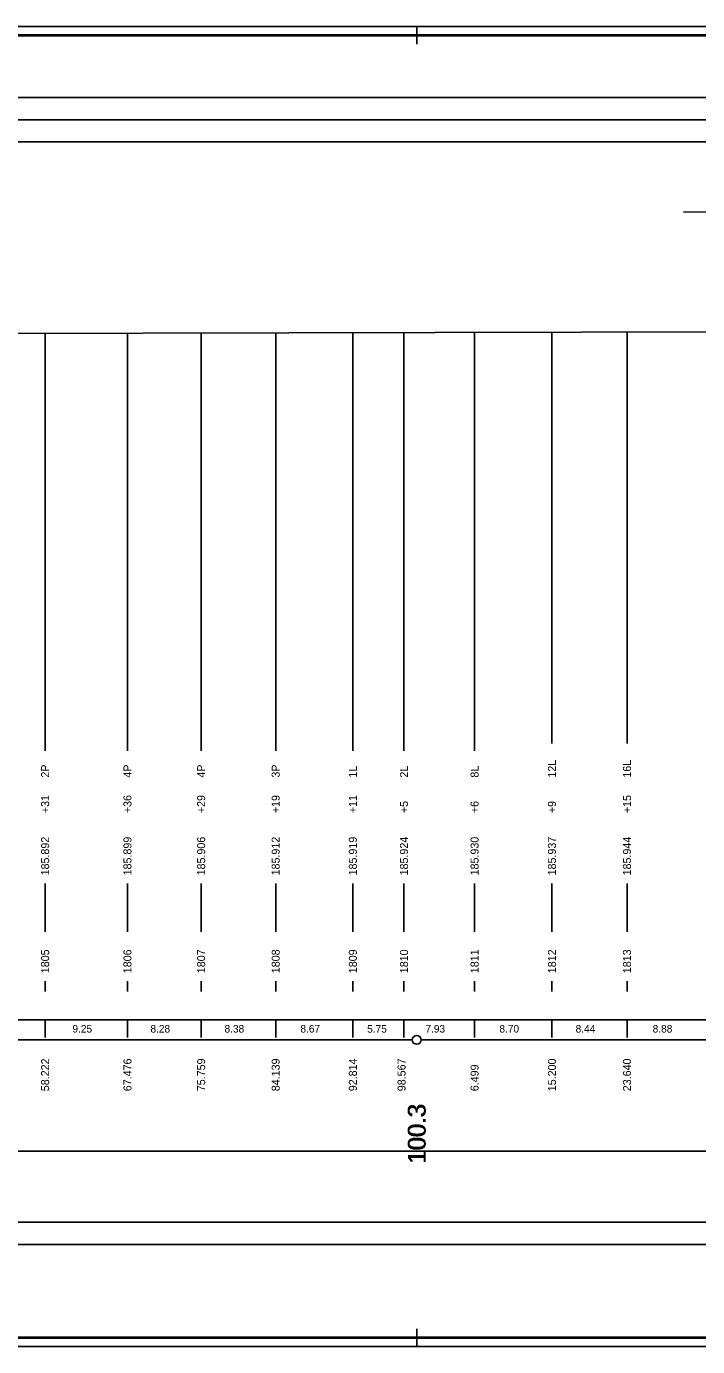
# Model space of a CAD drawing. Extents: x 0 to 10087, y -805 to 297.
# Drawn here: x 7892.2 to 8043.1, y 0 to 297 of the extents above; entities that cross this region are included whole.
import ezdxf

# ---------------------------------------------------------------- set-up
doc = ezdxf.new("R2010")
doc.units = 0
for name, color, linetype in [('CARKY_HODNOT', 7, 'Continuous'), ('KRIV1_CARA', 7, 'Continuous'), ('NIVELETA_CARA', 7, 'Continuous'), ('RAM', 7, 'Continuous'), ('REZERVA', 7, 'Continuous'), ('STAN_CARA', 7, 'Continuous'), ('STAN_PAS', 7, 'Continuous'), ('STAN_TEXT', 7, 'Continuous'), ('TEXT', 7, 'Continuous'), ('TXT_C_BODU', 7, 'Continuous')]:
    doc.layers.add(name, color=color, linetype=linetype)

msp = doc.modelspace()

# ---------------------------------------------------------------- linework, layer by layer
at = {"layer": 'CARKY_HODNOT'}
for p, q in [((7896.44, 138.35), (7896.44, 227.96)), ((7914.95, 138.35), (7914.95, 227.99)), ((7931.52, 138.35), (7931.52, 228.03)), ((7948.28, 138.35), (7948.28, 228.06)), ((7965.63, 138.35), (7965.63, 228.1)), ((7977.13, 138.35), (7977.13, 228.12)), ((7993, 138.35), (7993, 228.15)), ((8010.4, 138.35), (8010.4, 228.19)), ((8027.28, 138.35), (8027.28, 228.22)), ((7896.44, 134), (7896.44, 138.35)), ((7914.95, 134), (7914.95, 138.35)), ((7931.52, 134), (7931.52, 138.35)), ((7948.28, 134), (7948.28, 138.35)), ((7965.63, 134), (7965.63, 138.35)), ((7977.13, 134), (7977.13, 138.35)), ((7993, 134), (7993, 138.35)), ((8010.4, 135.65), (8010.4, 138.35)), ((8027.28, 135.65), (8027.28, 138.35)), ((7896.44, 93.3), (7896.44, 104.2)), ((7914.95, 93.3), (7914.95, 104.2)), ((7931.52, 93.3), (7931.52, 104.2)), ((7948.28, 93.3), (7948.28, 104.2)), ((7965.63, 93.3), (7965.63, 104.2)), ((7977.13, 93.3), (7977.13, 104.2)), ((7993, 93.3), (7993, 104.2)), ((8010.4, 93.3), (8010.4, 104.2)), ((8027.28, 93.3), (8027.28, 104.2)), ((7896.44, 79.9), (7896.44, 82.2)), ((7914.95, 79.9), (7914.95, 82.2)), ((7931.52, 79.9), (7931.52, 82.2)), ((7948.28, 79.9), (7948.28, 82.2)), ((7965.63, 79.9), (7965.63, 82.2)), ((7977.13, 79.9), (7977.13, 82.2)), ((7993, 79.9), (7993, 82.2)), ((8010.4, 79.9), (8010.4, 82.2)), ((8027.28, 79.9), (8027.28, 82.2))]:
    msp.add_line(p, q, dxfattribs=at)
at = {"layer": 'KRIV1_CARA'}
msp.add_line((7811.8, 44), (8321.33, 44), dxfattribs=at)
at = {"layer": 'NIVELETA_CARA'}
for p, q in [((300, 281), (8321.33, 281)), ((300, 276), (8321.33, 276)), ((300, 271), (8321.33, 271)), ((8067.97, 255.3), (8039.97, 255.24)), ((7721.21, 227.61), (8065.75, 228.3)), ((500, 28), (8321.33, 28)), ((500, 23), (8321.33, 23))]:
    msp.add_line(p, q, dxfattribs=at)
at = {"layer": 'RAM'}
for p, q in [((8636.33, 297), (0, 297)), ((7980, 293), (7980, 297)), ((8634.33, 295.1), (2, 295.1)), ((8634.33, 295), (2, 295)), ((8634.33, 294.9), (2, 294.9)), ((7980, 0), (7980, 4)), ((0, 0), (8636.33, 0)), ((2, 2.1), (8634.33, 2.1)), ((2, 2), (8634.33, 2)), ((2, 1.9), (8634.33, 1.9))]:
    msp.add_line(p, q, dxfattribs=at)
at = {"layer": 'REZERVA'}
msp.add_circle((7980, 69), 1, dxfattribs=at)
at = {"layer": 'STAN_CARA'}
for p, q in [((7781, 69), (7979, 69)), ((7981, 69), (8179, 69))]:
    msp.add_line(p, q, dxfattribs=at)
at = {"layer": 'STAN_PAS'}
for p, q in [((300, 73.5), (8321.33, 73.5)), ((7896.44, 69.5), (7896.44, 73.5)), ((7914.95, 69.5), (7914.95, 73.5)), ((7931.52, 69.5), (7931.52, 73.5)), ((7948.28, 69.5), (7948.28, 73.5)), ((7965.63, 69.5), (7965.63, 73.5)), ((7977.13, 69.5), (7977.13, 73.5)), ((7993, 69.5), (7993, 73.5)), ((8010.4, 69.5), (8010.4, 73.5)), ((8027.28, 69.5), (8027.28, 73.5))]:
    msp.add_line(p, q, dxfattribs=at)

# ---------------------------------------------------------------- texts
at = {"layer": 'STAN_TEXT'}
for s, p in [('9.25', (7902.58, 70.65)), ('8.28', (7920.12, 70.65)), ('8.38', (7936.78, 70.65)), ('8.67', (7953.84, 70.65)), ('5.75', (7968.84, 70.63)), ('7.93', (7981.95, 70.65)), ('8.70', (7998.58, 70.65)), ('8.44', (8015.72, 70.65)), ('8.88', (8033.04, 70.65))]:
    msp.add_text(s, height=1.7, dxfattribs=at).set_placement(p)
for s, height, p in [('58.222', 1.8, (7897.34, 57.45)), ('67.476', 1.8, (7915.85, 57.45)), ('75.759', 1.8, (7932.42, 57.45)), ('84.139', 1.8, (7949.18, 57.45)), ('92.814', 1.8, (7966.53, 57.45)), ('98.567', 1.8, (7977.48, 57.45)), ('6.499', 1.8, (7993.9, 57.45)), ('15.200', 1.8, (8011.3, 57.45)), ('23.640', 1.8, (8028.18, 57.45)), ('   100.3', 4, (7982, 36.84)), ('   100.3', 4, (7982, 36.74)), ('   100.3', 4, (7982, 36.64))]:
    msp.add_text(s, height=height, rotation=90, dxfattribs=at).set_placement(p)
at = {"layer": 'TEXT'}
for s, p in [('2P', (7897.34, 128)), ('4P', (7915.85, 128)), ('4P', (7932.42, 128)), ('3P', (7949.18, 128)), ('12L', (8011.3, 128)), ('16L', (8028.18, 128)), ('1L', (7966.53, 128)), ('2L', (7978.03, 128)), ('8L', (7993.9, 128)), ('+31', (7897.34, 120)), ('+36', (7915.85, 120)), ('+29', (7932.42, 120)), ('+19', (7949.18, 120)), ('+11', (7966.53, 120)), ('+5', (7978.03, 120)), ('+6', (7993.9, 120)), ('+9', (8011.3, 120)), ('+15', (8028.18, 120)), ('185.892', (7897.34, 106)), ('185.899', (7915.85, 106)), ('185.906', (7932.42, 106)), ('185.912', (7949.18, 106)), ('185.919', (7966.53, 106)), ('185.924', (7978.03, 106)), ('185.930', (7993.9, 106)), ('185.937', (8011.3, 106)), ('185.944', (8028.18, 106))]:
    msp.add_text(s, height=1.8, rotation=90, dxfattribs=at).set_placement(p)
at = {"layer": 'TXT_C_BODU'}
for s, p in [('1805', (7897.34, 84)), ('1806', (7915.85, 84)), ('1807', (7932.42, 84)), ('1808', (7949.18, 84)), ('1809', (7966.53, 84)), ('1810', (7978.03, 84)), ('1811', (7993.9, 84)), ('1812', (8011.3, 84)), ('1813', (8028.18, 84))]:
    msp.add_text(s, height=1.8, rotation=90, dxfattribs=at).set_placement(p)

doc.saveas('drawing.dxf')
